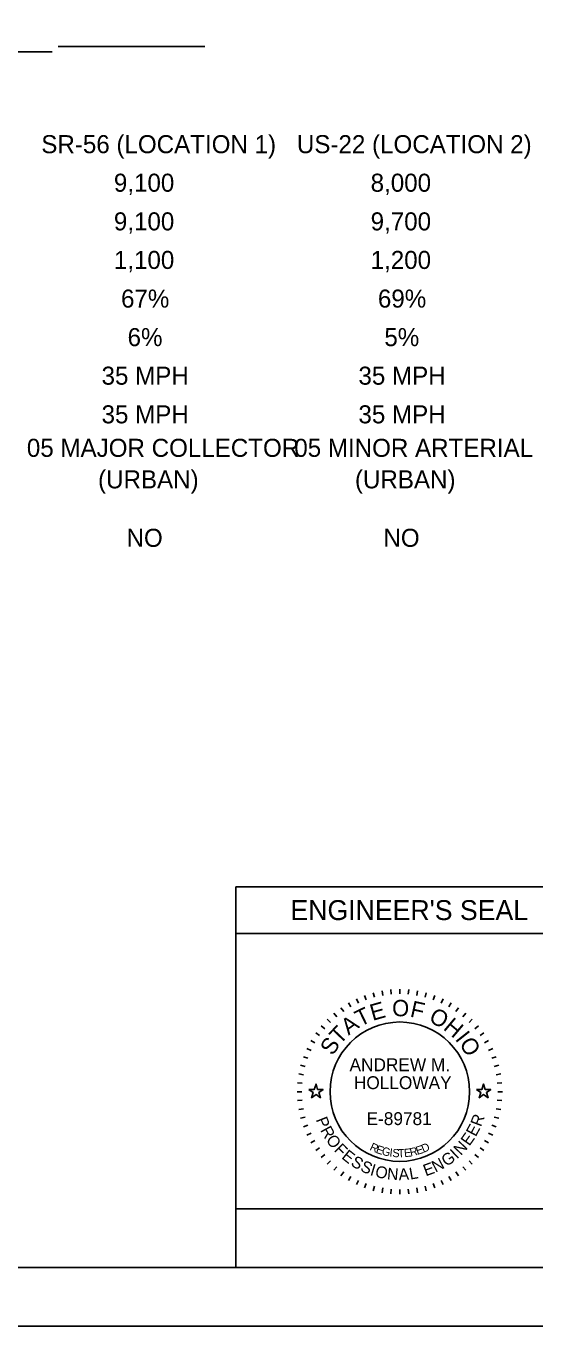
# Model space of a CAD drawing. Extents: x 0 to 34, y 0 to 22.
# Drawn here: x 7.48 to 11.82, y 0 to 11.1 of the extents above; entities that cross this region are included whole.
import ezdxf

# ---------------------------------------------------------------- set-up
doc = ezdxf.new("R2010")
doc.units = 0
for name, color, linetype in [('Default', 7, 'Continuous'), ('SH_Border', 7, 'Continuous'), ('SH_Cut_Line', 7, 'Continuous'), ('SH_Data', 7, 'Continuous'), ('SH_Text', 7, 'Continuous')]:
    doc.layers.add(name, color=color, linetype=linetype)

msp = doc.modelspace()

# ---------------------------------------------------------------- linework, layer by layer
at = {"layer": 'Default'}
for points in [[(9.887, 2.02), (9.934, 2.02), (9.949, 2.065), (9.963, 2.02), (10.01, 2.02), (9.972, 1.992), (9.987, 1.948), (9.949, 1.975), (9.911, 1.948), (9.925, 1.992)], [(11.317, 2.02), (11.364, 2.02), (11.379, 2.065), (11.393, 2.02), (11.44, 2.02), (11.402, 1.992), (11.417, 1.948), (11.379, 1.975), (11.341, 1.948), (11.355, 1.992)]]:
    msp.add_lwpolyline(points, close=True, dxfattribs=at)
at = {"layer": 'SH_Border'}
msp.add_lwpolyline([(1.5, 21.5), (33.5, 21.5), (33.5, 0.5), (1.5, 0.5)], close=True, dxfattribs=at)
at = {"layer": 'SH_Cut_Line'}
msp.add_lwpolyline([(0, 0), (34, 0), (34, 22), (0, 22)], close=True, dxfattribs=at)
at = {"layer": 'SH_Data'}
for p, q in [((7.7, 10.877), (3.347, 10.877)), ((9, 10.922), (7.75, 10.922)), ((12.064, 3.75), (9.264, 3.75)), ((9.264, 3.75), (9.264, 0.5)), ((12.064, 3.35), (9.264, 3.35)), ((10.294, 2.793), (10.311, 2.757)), ((10.364, 2.822), (10.378, 2.785)), ((10.437, 2.845), (10.447, 2.807)), ((10.512, 2.862), (10.519, 2.822)), ((10.587, 2.872), (10.591, 2.832)), ((10.664, 2.875), (10.664, 2.835)), ((10.74, 2.872), (10.736, 2.832)), ((10.816, 2.862), (10.809, 2.822)), ((10.89, 2.845), (10.88, 2.807)), ((10.963, 2.822), (10.949, 2.785)), ((11.033, 2.793), (11.016, 2.757)), ((10.101, 2.67), (10.127, 2.64)), ((10.162, 2.717), (10.185, 2.684)), ((10.226, 2.758), (10.246, 2.723)), ((11.101, 2.758), (11.081, 2.723)), ((11.165, 2.717), (11.143, 2.684)), ((11.226, 2.67), (11.2, 2.64)), ((9.993, 2.562), (10.024, 2.537)), ((10.045, 2.619), (10.073, 2.59)), ((11.282, 2.619), (11.254, 2.59)), ((11.334, 2.562), (11.303, 2.537)), ((9.947, 2.502), (9.98, 2.479)), ((11.38, 2.502), (11.348, 2.479)), ((9.871, 2.37), (9.907, 2.353)), ((9.906, 2.438), (9.94, 2.418)), ((11.421, 2.438), (11.387, 2.418)), ((11.457, 2.37), (11.42, 2.353)), ((9.818, 2.226), (9.857, 2.216)), ((9.841, 2.299), (9.879, 2.286)), ((11.486, 2.299), (11.448, 2.286)), ((11.509, 2.226), (11.47, 2.216)), ((9.802, 2.152), (9.841, 2.145)), ((11.525, 2.152), (11.486, 2.145)), ((9.789, 2), (9.829, 2)), ((9.792, 2.076), (9.832, 2.073)), ((11.535, 2.076), (11.495, 2.073)), ((11.539, 2), (11.499, 2)), ((9.792, 1.924), (9.832, 1.927)), ((11.535, 1.924), (11.495, 1.927)), ((9.802, 1.848), (9.841, 1.855)), ((9.818, 1.774), (9.857, 1.784)), ((11.509, 1.774), (11.47, 1.784)), ((11.525, 1.848), (11.486, 1.855)), ((9.841, 1.701), (9.879, 1.714)), ((11.486, 1.701), (11.448, 1.714)), ((9.871, 1.63), (9.907, 1.647)), ((9.906, 1.563), (9.94, 1.583)), ((11.421, 1.563), (11.387, 1.583)), ((11.457, 1.63), (11.42, 1.647)), ((9.947, 1.498), (9.98, 1.521)), ((9.993, 1.438), (10.024, 1.463)), ((11.334, 1.438), (11.303, 1.463)), ((11.38, 1.498), (11.348, 1.521)), ((10.045, 1.381), (10.073, 1.41)), ((10.101, 1.33), (10.127, 1.36)), ((11.226, 1.33), (11.2, 1.36)), ((11.282, 1.381), (11.254, 1.41)), ((10.162, 1.283), (10.185, 1.316)), ((10.226, 1.242), (10.246, 1.277)), ((10.294, 1.207), (10.311, 1.243)), ((11.033, 1.207), (11.016, 1.243)), ((11.101, 1.242), (11.081, 1.277)), ((11.165, 1.283), (11.143, 1.316)), ((10.364, 1.178), (10.378, 1.215)), ((10.437, 1.155), (10.447, 1.193)), ((10.512, 1.138), (10.519, 1.178)), ((10.587, 1.128), (10.591, 1.168)), ((10.664, 1.125), (10.664, 1.165)), ((10.74, 1.128), (10.736, 1.168)), ((10.816, 1.138), (10.809, 1.178)), ((10.89, 1.155), (10.88, 1.193)), ((10.963, 1.178), (10.949, 1.215)), ((9.264, 0.5), (12.064, 0.5)), ((12.064, 0.5), (9.264, 0.5)), ((12.064, 0.5), (9.264, 0.5))]:
    msp.add_line(p, q, dxfattribs=at)
msp.add_lwpolyline([(12.064, 0.5), (12.064, 1), (9.264, 1), (9.264, 0.5)], close=True, dxfattribs=at)
msp.add_circle((10.664, 2), 0.595, dxfattribs=at)

# ---------------------------------------------------------------- texts
for s, height, p in [("ENGINEER'S SEAL", 0.17, (9.731, 3.465)), ('ANDREW M.', 0.11, (10.235, 2.175)), ('HOLLOWAY', 0.11, (10.272, 2.022)), ('E-89781', 0.11, (10.38, 1.715))]:
    msp.add_text(s, height=height, dxfattribs=at).set_placement(p)
for s, height, rotation, p in [('O', 0.14, 359.7812, (10.598, 2.644)), ('F', 0.14, 347.4362, (10.745, 2.642)), ('T', 0.14, 25.7167, (10.325, 2.552)), ('E', 0.14, 15.7571, (10.432, 2.604)), ('O', 0.14, 332.2586, (10.903, 2.602)), ('T', 0.14, 46.4344, (10.152, 2.396)), ('A', 0.14, 36.4747, (10.227, 2.478)), ('H', 0.14, 319.9136, (11.027, 2.536)), ('S', 0.14, 57.1924, (10.092, 2.301)), ('I', 0.14, 308.367, (11.13, 2.448)), ('O', 0.14, 303.1491, (11.166, 2.409)), ('P', 0.1, 291.494, (9.946, 1.762)), ('R', 0.1, 69.2322, (11.356, 1.695)), ('R', 0.1, 298.7311, (9.983, 1.672)), ('E', 0.1, 61.9951, (11.311, 1.61)), ('O', 0.1, 306.4666, (10.029, 1.588)), ('F', 0.1, 314.7068, (10.098, 1.498)), ('R', 0.07, 334.487, (10.401, 1.505)), ('D', 0.07, 23.3052, (10.865, 1.477)), ('N', 0.1, 47.0224, (11.184, 1.451)), ('E', 0.1, 54.758, (11.257, 1.531)), ('E', 0.1, 321.4393, (10.161, 1.435)), ('S', 0.1, 328.6764, (10.238, 1.375)), ('E', 0.07, 341.04, (10.454, 1.48)), ('G', 0.07, 347.4752, (10.505, 1.462)), ('I', 0.07, 353.7858, (10.573, 1.447)), ('S', 0.07, 356.8926, (10.599, 1.443)), ('T', 0.07, 3.0061, (10.649, 1.439)), ('E', 0.07, 6.0117, (10.703, 1.441)), ('R', 0.07, 11.9184, (10.756, 1.447)), ('E', 0.07, 17.6836, (10.813, 1.46)), ('G', 0.1, 35.0469, (11.062, 1.357)), ('I', 0.1, 43.287, (11.15, 1.421)), ('S', 0.1, 335.9134, (10.32, 1.327)), ('I', 0.1, 343.1505, (10.404, 1.29)), ('O', 0.1, 346.8859, (10.447, 1.275)), ('N', 0.1, 355.1261, (10.552, 1.252)), ('A', 0.1, 2.8617, (10.656, 1.244)), ('L', 0.1, 10.0987, (10.753, 1.249)), ('E', 0.1, 20.0742, (10.885, 1.277)), ('N', 0.1, 27.3113, (10.968, 1.308))]:
    msp.add_text(s, height=height, rotation=rotation, dxfattribs=at).set_placement(p)
at = {"layer": 'SH_Text'}
for s, p in [('SR-56 (LOCATION 1)', (7.606, 10.011)), ('US-22 (LOCATION 2)', (9.786, 10.011)), ('9,100', (8.225, 9.682)), ('8,000', (10.415, 9.682)), ('9,100', (8.225, 9.352)), ('9,700', (10.415, 9.352)), ('1,100', (8.225, 9.023)), ('1,200', (10.415, 9.023)), ('67%', (8.286, 8.693)), ('69%', (10.477, 8.693)), ('6%', (8.342, 8.364)), ('5%', (10.532, 8.364)), ('35 MPH', (8.12, 8.035)), ('35 MPH', (10.311, 8.035)), ('35 MPH', (8.12, 7.705)), ('35 MPH', (10.311, 7.705)), ('05 MAJOR COLLECTOR ', (7.483, 7.419)), ('05 MINOR ARTERIAL ', (9.764, 7.419)), ('(URBAN)', (8.09, 7.15)), ('(URBAN)', (10.281, 7.15)), ('NO', (8.333, 6.651)), ('NO', (10.524, 6.651))]:
    msp.add_text(s, height=0.154, dxfattribs=at).set_placement(p)

doc.saveas('drawing.dxf')
